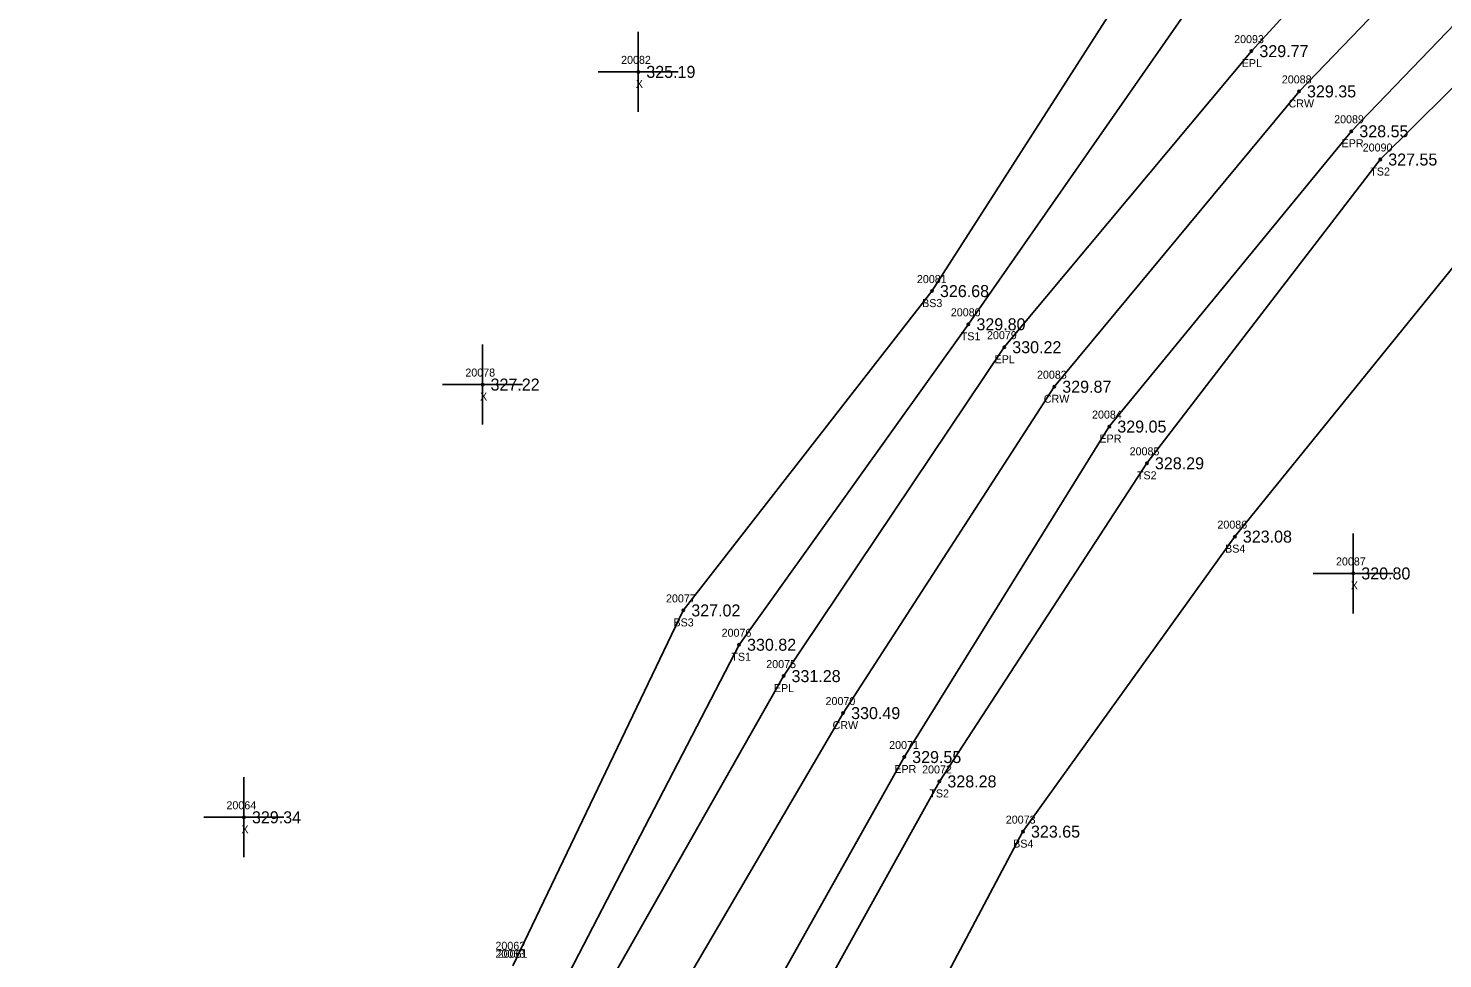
# Model space of a CAD drawing. Extents: x 2231109 to 2232328, y 1035718 to 1036919.
# Drawn here: x 2231228.7 to 2231405.5, y 1036185.9 to 1036302.1 of the extents above; entities that cross this region are included whole.
import ezdxf

# ---------------------------------------------------------------- set-up
doc = ezdxf.new("R2010")
doc.units = 0
for name, color, linetype in [('RD_DTM_BkLn1', 7, 'Continuous'), ('RD_DTM_BkLn2', 7, 'Continuous'), ('RD_DTM_BkLn_txCode', 7, 'Continuous'), ('RD_EX_H2O_txCode', 7, 'Continuous'), ('RD_EX_Misc', 7, 'Continuous'), ('RD_EX_Misc_txCode', 7, 'Continuous'), ('RD_EX_Road', 7, 'Continuous'), ('RD_EX_Road_txCode', 7, 'Continuous'), ('RD_EX_TX_Misc_ELEV', 7, 'Continuous'), ('RD_EX_TX_Road_ELEV', 7, 'Continuous'), ('RD_HC_Survey_ELEV', 7, 'Continuous'), ('RD_HC_Survey_txCode', 7, 'Continuous'), ('RD_SMD_Locator', 7, 'Continuous')]:
    doc.layers.add(name, color=color, linetype=linetype)

msp = doc.modelspace()

# ---------------------------------------------------------------- linework, layer by layer
at = {"layer": 'RD_DTM_BkLn1'}
msp.add_lwpolyline([(2231168.25, 1035745.18), (2231197.3, 1035848.59), (2231226.32, 1035944.04), (2231254.24, 1036037.31), (2231285.91, 1036129.66), (2231306.91, 1036176.17), (2231330.56, 1036216.58), (2231356.95, 1036257.36), (2231387.54, 1036294.26), (2231422.35, 1036330.42), (2231422.35, 1036330.4), (2231458.4, 1036362.33), (2231503.71, 1036399.67), (2231541.46, 1036424.96)], dxfattribs=at)
at = {"layer": 'RD_DTM_BkLn2'}
for points in [[(2231289.28, 1036185.01), (2231310.58, 1036229.41), (2231341.66, 1036269.31), (2231367.87, 1036310.22), (2231401.74, 1036350.83), (2231444.02, 1036383.07), (2231489.16, 1036422.11), (2231530.24, 1036446.93), (2231543.7, 1036441.83)], [(2231153.91, 1035749.54), (2231183.9, 1035852.41), (2231210.94, 1035948.08), (2231242.08, 1036041.75), (2231274.33, 1036134.79), (2231295.17, 1036181.88), (2231317.55, 1036225.12), (2231346.22, 1036265.16), (2231373.72, 1036304.6), (2231409.94, 1036342.78), (2231447.25, 1036376.56), (2231493.69, 1036413.26), (2231528.08, 1036438.61), (2231532.84, 1036438.24), (2231534.71, 1036436.33)], [(2231276.31, 1036031.77), (2231313.52, 1036118.16), (2231333.31, 1036164.6), (2231353.04, 1036201.77), (2231379.52, 1036238.63), (2231408.34, 1036274.21), (2231439.77, 1036308.83), (2231482.36, 1036339.48), (2231523.58, 1036374.84), (2231550.15, 1036393.87), (2231557.23, 1036405.65), (2231555.87, 1036413.6)], [(2231180.99, 1035741.83), (2231209.96, 1035844.49), (2231237.45, 1035939.8), (2231265.71, 1036032.03), (2231300.77, 1036123.1), (2231321.14, 1036169.41), (2231342.59, 1036208.04), (2231368.53, 1036247.79), (2231397.69, 1036285.75), (2231431.64, 1036319.41), (2231468.01, 1036352.78), (2231515.06, 1036385.58), (2231547.14, 1036404.2), (2231548.89, 1036408.2), (2231548.45, 1036412.54)]]:
    msp.add_lwpolyline(points, dxfattribs=at)
at = {"layer": 'RD_EX_Misc'}
for p, q in [((2231304.96, 1036291.7), (2231304.96, 1036301.7)), ((2231299.96, 1036296.7), (2231309.96, 1036296.7)), ((2231285.49, 1036252.63), (2231285.49, 1036262.63)), ((2231280.49, 1036257.63), (2231290.49, 1036257.63)), ((2231394.32, 1036229.03), (2231394.32, 1036239.03)), ((2231389.32, 1036234.03), (2231399.32, 1036234.03)), ((2231255.67, 1036198.56), (2231255.67, 1036208.56)), ((2231250.67, 1036203.56), (2231260.67, 1036203.56))]:
    msp.add_line(p, q, dxfattribs=at)
at = {"layer": 'RD_EX_Road'}
for points in [[(2231158.42, 1035748.11), (2231188.37, 1035851.38), (2231216.59, 1035946.92), (2231244.77, 1036040.72), (2231278.59, 1036133.31), (2231299.55, 1036179.73), (2231323.11, 1036221.2), (2231350.7, 1036262.3), (2231381.59, 1036299.29), (2231415.97, 1036336.9), (2231452.94, 1036369.74), (2231498.19, 1036405.3), (2231537.2, 1036432.57), (2231541.46, 1036424.96)], [(2231176.43, 1035742.89), (2231206.61, 1035845.83), (2231234.19, 1035940.65), (2231261.92, 1036033.75), (2231294.68, 1036125.28), (2231316.11, 1036171.75), (2231338.19, 1036211.09), (2231363.83, 1036252.38), (2231394.08, 1036289.28), (2231427.67, 1036324.2), (2231464.37, 1036355.5), (2231508.96, 1036392.41), (2231546.55, 1036416.22), (2231541.46, 1036424.96)]]:
    msp.add_lwpolyline(points, dxfattribs=at)
at = {"layer": 'RD_SMD_Locator'}
for centre in [(2231381.59, 1036299.29), (2231304.96, 1036296.7), (2231387.54, 1036294.26), (2231394.08, 1036289.28), (2231397.69, 1036285.75), (2231341.66, 1036269.31), (2231346.22, 1036265.16), (2231350.7, 1036262.3), (2231285.49, 1036257.63), (2231356.95, 1036257.36), (2231363.83, 1036252.38), (2231368.53, 1036247.79), (2231379.52, 1036238.63), (2231394.32, 1036234.03), (2231310.58, 1036229.41), (2231317.55, 1036225.12), (2231323.11, 1036221.2), (2231330.56, 1036216.58), (2231338.19, 1036211.09), (2231342.59, 1036208.04), (2231255.67, 1036203.56), (2231353.04, 1036201.77)]:
    msp.add_circle(centre, 0.15, dxfattribs=at)

# ---------------------------------------------------------------- texts
at = {"layer": 'RD_DTM_BkLn_txCode'}
for s, p in [('20090', (2231395.5, 1036286.75)), ('TS2', (2231396.45, 1036283.75)), ('20081', (2231339.78, 1036270.31)), ('BS3', (2231340.43, 1036267.31)), ('20080', (2231344.02, 1036266.16)), ('TS1', (2231345.26, 1036263.16)), ('20085', (2231366.37, 1036248.79)), ('TS2', (2231367.28, 1036245.79)), ('20086', (2231377.34, 1036239.63)), ('BS4', (2231378.3, 1036236.63)), ('20077', (2231308.42, 1036230.41)), ('BS3', (2231309.35, 1036227.41)), ('20076', (2231315.37, 1036226.12)), ('TS1', (2231316.59, 1036223.12)), ('20072', (2231340.43, 1036209.04)), ('TS2', (2231341.34, 1036206.04)), ('20073', (2231350.89, 1036202.77)), ('BS4', (2231351.81, 1036199.77)), ('20063', (2231287.1, 1036186.01)), ('20061', (2231287.38, 1036186.01))]:
    msp.add_text(s, height=1, dxfattribs=at).set_placement(p)
at = {"layer": 'RD_EX_H2O_txCode'}
msp.add_text('20062', height=1, dxfattribs=at).set_placement((2231287.1, 1036187.01))
at = {"layer": 'RD_EX_Misc_txCode'}
for s, p in [('20082', (2231302.81, 1036297.7)), ('X', (2231304.65, 1036294.7)), ('20078', (2231283.34, 1036258.63)), ('X', (2231285.18, 1036255.63)), ('20087', (2231392.16, 1036235.03)), ('X', (2231394.01, 1036232.03)), ('20064', (2231253.48, 1036204.56)), ('X', (2231255.35, 1036201.56))]:
    msp.add_text(s, height=1, dxfattribs=at).set_placement(p)
at = {"layer": 'RD_EX_Road_txCode'}
for s, p in [('20093', (2231379.43, 1036300.29)), ('EPL', (2231380.38, 1036297.29)), ('20089', (2231391.93, 1036290.28)), ('EPR', (2231392.86, 1036287.28)), ('20079', (2231348.54, 1036263.3)), ('EPL', (2231349.49, 1036260.3)), ('20084', (2231361.67, 1036253.38)), ('EPR', (2231362.6, 1036250.38)), ('20075', (2231320.95, 1036222.2)), ('EPL', (2231321.9, 1036219.2)), ('20071', (2231336.31, 1036212.09)), ('EPR', (2231336.96, 1036209.09))]:
    msp.add_text(s, height=1, dxfattribs=at).set_placement(p)
at = {"layer": 'RD_EX_TX_Misc_ELEV'}
for s, p in [('325.19', (2231305.96, 1036295.95)), ('327.55', (2231398.69, 1036285)), ('326.68', (2231342.66, 1036268.56)), ('329.80', (2231347.22, 1036264.41)), ('327.22', (2231286.49, 1036256.88)), ('328.29', (2231369.53, 1036247.04)), ('323.08', (2231380.52, 1036237.88)), ('320.80', (2231395.32, 1036233.28)), ('327.02', (2231311.58, 1036228.66)), ('330.82', (2231318.55, 1036224.37)), ('328.28', (2231343.59, 1036207.29)), ('329.34', (2231256.67, 1036202.81)), ('323.65', (2231354.04, 1036201.02))]:
    msp.add_text(s, height=1.5, dxfattribs=at).set_placement(p)
at = {"layer": 'RD_EX_TX_Road_ELEV'}
for s, p in [('329.77', (2231382.59, 1036298.54)), ('328.55', (2231395.08, 1036288.53)), ('330.22', (2231351.7, 1036261.55)), ('329.05', (2231364.83, 1036251.63)), ('331.28', (2231324.11, 1036220.45)), ('329.55', (2231339.19, 1036210.34))]:
    msp.add_text(s, height=1.5, dxfattribs=at).set_placement(p)
at = {"layer": 'RD_HC_Survey_ELEV'}
for s, p in [('329.35', (2231388.54, 1036293.51)), ('329.87', (2231357.95, 1036256.61)), ('330.49', (2231331.56, 1036215.83))]:
    msp.add_text(s, height=1.5, dxfattribs=at).set_placement(p)
at = {"layer": 'RD_HC_Survey_txCode'}
for s, p in [('20088', (2231385.39, 1036295.26)), ('CRW', (2231386.23, 1036292.26)), ('20083', (2231354.79, 1036258.36)), ('CRW', (2231355.64, 1036255.36)), ('20070', (2231328.36, 1036217.58)), ('CRW', (2231329.24, 1036214.58))]:
    msp.add_text(s, height=1, dxfattribs=at).set_placement(p)

doc.saveas('drawing.dxf')
